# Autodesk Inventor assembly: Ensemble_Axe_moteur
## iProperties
Shininess: 64.0
Length Units: 11269
Angle Units: 11279
Time Units: 11290
Mass Units: 11283
Length Display Precision: 3
Angle Display Precision: 2
Compacted: True
Created: 2004-05
Part Number: Ensemble_Axe_moteur
Document SubType Name: Assembly
Designer: David
Density: 0.0
Volumn: 0.0
Area: 0.0
PropertySet Name: Model Information
Control State: 0
Master: False
Checked Out: False
Author: David
